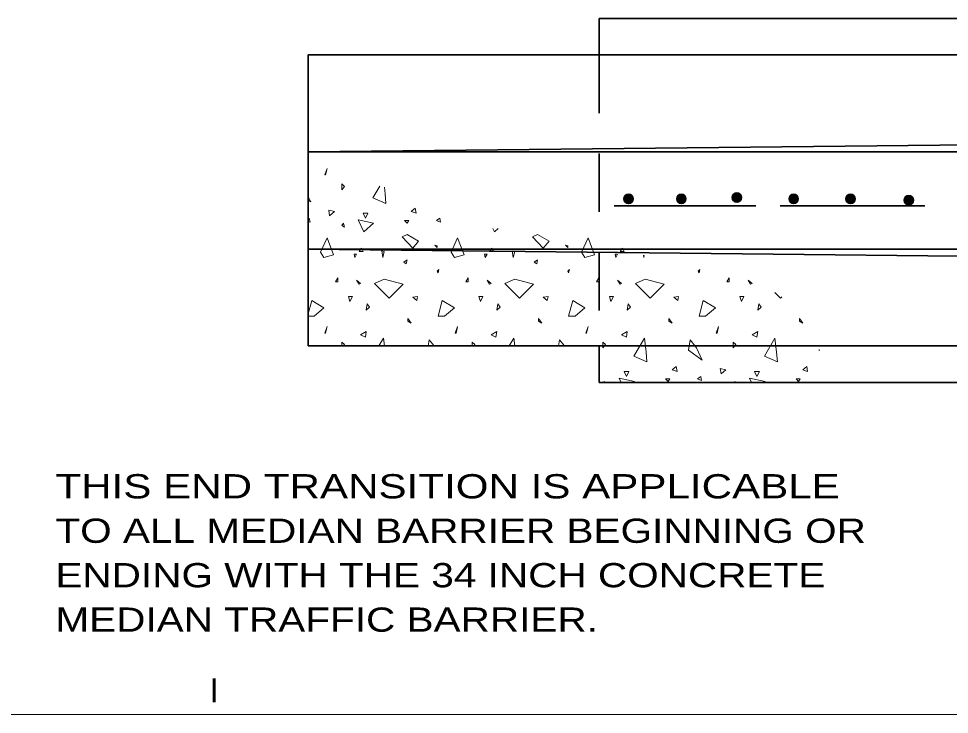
# Model space of a CAD drawing. Extents: x -11.7 to -4.5, y 8.6 to 18.8.
# Drawn here: x -9.437 to -7.133, y 16.995 to 18.716 of the extents above; entities that cross this region are included whole.
import ezdxf

# ---------------------------------------------------------------- set-up
doc = ezdxf.new("R2010")
doc.units = 0
doc.header["$LTSCALE"] = 0.024
doc.linetypes.add('LONG_DASHED', pattern=[7.5, 6, -1.5])
for name, color, linetype, lineweight in [('1', 7, 'Continuous', 35), ('10', 7, 'Continuous', 13), ('12', 7, 'Continuous', 53), ('6', 7, 'Continuous', 13)]:
    doc.layers.add(name, color=color, linetype=linetype, lineweight=lineweight)

msp = doc.modelspace()

# ---------------------------------------------------------------- linework, layer by layer
at = {"layer": '1'}
for p, q in [((-7.99983, 18.6265), (-7.99983, 18.7165)), ((-7.99983, 18.7165), (-5.59767, 18.7165)), ((-5.95783, 18.4165), (-8.71983, 18.3865)), ((-8.71983, 18.3865), (-5.95783, 18.3865)), ((-7.9625, 18.2535), (-7.61233, 18.2535)), ((-7.552, 18.2535), (-7.19333, 18.2535)), ((-8.71983, 18.14633), (-5.95783, 18.14633)), ((-8.71983, 17.90633), (-5.59933, 17.90633)), ((-7.99983, 17.81633), (-7.99983, 17.90633)), ((-7.99983, 17.81633), (-5.59767, 17.81633))]:
    msp.add_line(p, q, dxfattribs=at)
at = {"layer": '1', "linetype": 'LONG_DASHED'}
msp.add_line((-7.99983, 18.6265), (-7.99983, 17.90633), dxfattribs=at)
at = {"layer": '1'}
for points in [[(-8.71983, 17.90633), (-8.71983, 18.6265), (-5.59933, 18.6265)], [(-5.59933, 18.11633), (-5.95783, 18.11633), (-8.71983, 18.14633)]]:
    msp.add_lwpolyline(points, dxfattribs=at)
for centre, radius in [((-7.92702, 18.27033), 0.01145), ((-7.92712, 18.27042), 0.01068), ((-7.92814, 18.27042), 0.00926), ((-7.92699, 18.27015), 0.0103), ((-7.92669, 18.26967), 0.0101), ((-7.92674, 18.27003), 0.0094), ((-7.92777, 18.27087), 0.00766), ((-7.92649, 18.26997), 0.0089), ((-7.92642, 18.26972), 0.00843), ((-7.92795, 18.26997), 0.00665), ((-7.92629, 18.2696), 0.00805), ((-7.92642, 18.2694), 0.00767), ((-7.92852, 18.2696), 0.00531), ((-7.92622, 18.2694), 0.00747), ((-7.92636, 18.26952), 0.00722), ((-7.92604, 18.26934), 0.0069), ((-7.92597, 18.26947), 0.00646), ((-7.92764, 18.26985), 0.00429), ((-7.92591, 18.26954), 0.00601), ((-7.92591, 18.26967), 0.00551), ((-7.92584, 18.26952), 0.00519), ((-7.92584, 18.26947), 0.00468), ((-7.92564, 18.26907), 0.00448), ((-7.79632, 18.27033), 0.01145), ((-7.79642, 18.27042), 0.01068), ((-7.79744, 18.27042), 0.00926), ((-7.79629, 18.27015), 0.0103), ((-7.79598, 18.26967), 0.0101), ((-7.79604, 18.27003), 0.0094), ((-7.79706, 18.27087), 0.00766), ((-7.79579, 18.26997), 0.0089), ((-7.79571, 18.26972), 0.00843), ((-7.79724, 18.26997), 0.00665), ((-7.79559, 18.2696), 0.00805), ((-7.79571, 18.2694), 0.00767), ((-7.79782, 18.2696), 0.00531), ((-7.79552, 18.2694), 0.00747), ((-7.79566, 18.26952), 0.00722), ((-7.79534, 18.26934), 0.0069), ((-7.79526, 18.26947), 0.00646), ((-7.79694, 18.26985), 0.00429), ((-7.79521, 18.26954), 0.00601), ((-7.79521, 18.26967), 0.00551), ((-7.79514, 18.26952), 0.00519), ((-7.79514, 18.26947), 0.00468), ((-7.79494, 18.26907), 0.00448), ((-7.65894, 18.27369), 0.01145), ((-7.65903, 18.27378), 0.01068), ((-7.66006, 18.27378), 0.00926), ((-7.65891, 18.27351), 0.0103), ((-7.6586, 18.27303), 0.0101), ((-7.65866, 18.27339), 0.0094), ((-7.65968, 18.27423), 0.00766), ((-7.6584, 18.27333), 0.0089), ((-7.65833, 18.27308), 0.00843), ((-7.65986, 18.27333), 0.00665), ((-7.65821, 18.27296), 0.00805), ((-7.65833, 18.27276), 0.00767), ((-7.66044, 18.27296), 0.00531), ((-7.65813, 18.27276), 0.00747), ((-7.65828, 18.27288), 0.00722), ((-7.65795, 18.2727), 0.0069), ((-7.65788, 18.27283), 0.00646), ((-7.65956, 18.27321), 0.00429), ((-7.65783, 18.2729), 0.00601), ((-7.65783, 18.27303), 0.00551), ((-7.65776, 18.27288), 0.00519), ((-7.65776, 18.27283), 0.00468), ((-7.65756, 18.27243), 0.00448), ((-7.65745, 18.27238), 0.00409), ((-7.65745, 18.27249), 0.00359), ((-7.65731, 18.27258), 0.00346), ((-7.65731, 18.27225), 0.00319), ((-7.65718, 18.27251), 0.00306), ((-7.65713, 18.27243), 0.00262), ((-7.65731, 18.27263), 0.00218), ((-7.65705, 18.27236), 0.00194), ((-7.65698, 18.27238), 0.00161), ((-7.65686, 18.27231), 0.00122), ((-7.65686, 18.27243), 0.00108), ((-7.65648, 18.27238), 0.00136), ((-7.51819, 18.27037), 0.01145), ((-7.51829, 18.27046), 0.01068), ((-7.51932, 18.27046), 0.00926), ((-7.51817, 18.27019), 0.0103), ((-7.51786, 18.26971), 0.0101), ((-7.51791, 18.27007), 0.0094), ((-7.51894, 18.27091), 0.00766), ((-7.51766, 18.27001), 0.0089), ((-7.51759, 18.26976), 0.00843), ((-7.51912, 18.27001), 0.00665), ((-7.51746, 18.26964), 0.00805), ((-7.51759, 18.26944), 0.00767), ((-7.5197, 18.26964), 0.00531), ((-7.51739, 18.26944), 0.00747), ((-7.51754, 18.26956), 0.00722), ((-7.51721, 18.26938), 0.0069), ((-7.51714, 18.26951), 0.00646), ((-7.51709, 18.26958), 0.00601), ((-7.51881, 18.26989), 0.00429), ((-7.51709, 18.26971), 0.00551), ((-7.51701, 18.26956), 0.00519), ((-7.51701, 18.26951), 0.00468), ((-7.51682, 18.26911), 0.00448), ((-7.37745, 18.27037), 0.01145), ((-7.37755, 18.27046), 0.01068), ((-7.37858, 18.27046), 0.00926), ((-7.37742, 18.27019), 0.0103), ((-7.37712, 18.26971), 0.0101), ((-7.37717, 18.27007), 0.0094), ((-7.3782, 18.27091), 0.00766), ((-7.37692, 18.27001), 0.0089), ((-7.37685, 18.26976), 0.00843), ((-7.37838, 18.27001), 0.00665), ((-7.37672, 18.26964), 0.00805), ((-7.37685, 18.26944), 0.00767), ((-7.37895, 18.26964), 0.00531), ((-7.37665, 18.26944), 0.00747), ((-7.37679, 18.26956), 0.00722), ((-7.37647, 18.26938), 0.0069), ((-7.3764, 18.26951), 0.00646), ((-7.37807, 18.26989), 0.00429), ((-7.37634, 18.26958), 0.00601), ((-7.37634, 18.26971), 0.00551), ((-7.37627, 18.26956), 0.00519), ((-7.37627, 18.26951), 0.00468), ((-7.37607, 18.26911), 0.00448), ((-7.23335, 18.26701), 0.01145), ((-7.23345, 18.2671), 0.01068), ((-7.23447, 18.2671), 0.00926), ((-7.23332, 18.26683), 0.0103), ((-7.23301, 18.26635), 0.0101), ((-7.23307, 18.26671), 0.0094), ((-7.23409, 18.26755), 0.00766), ((-7.23282, 18.26665), 0.0089), ((-7.23274, 18.2664), 0.00843), ((-7.23262, 18.26628), 0.00805), ((-7.23274, 18.26608), 0.00767), ((-7.23255, 18.26608), 0.00747), ((-7.92553, 18.26902), 0.00409), ((-7.92553, 18.26913), 0.00359), ((-7.92539, 18.26922), 0.00346), ((-7.92539, 18.26889), 0.00319), ((-7.92526, 18.26915), 0.00306), ((-7.92521, 18.26907), 0.00262), ((-7.92539, 18.26927), 0.00218), ((-7.92514, 18.269), 0.00194), ((-7.92506, 18.26902), 0.00161), ((-7.92494, 18.26895), 0.00122), ((-7.92494, 18.26907), 0.00108), ((-7.92456, 18.26902), 0.00136), ((-7.92496, 18.26907), 0.000706), ((-7.92508, 18.26907), 0.000332), ((-7.92481, 18.26907), 0.000211), ((-7.79483, 18.26902), 0.00409), ((-7.79483, 18.26913), 0.00359), ((-7.79469, 18.26922), 0.00346), ((-7.79469, 18.26889), 0.00319), ((-7.79456, 18.26915), 0.00306), ((-7.79451, 18.26907), 0.00262), ((-7.79469, 18.26927), 0.00218), ((-7.79444, 18.269), 0.00194), ((-7.79436, 18.26902), 0.00161), ((-7.79424, 18.26895), 0.00122), ((-7.79424, 18.26907), 0.00108), ((-7.79386, 18.26902), 0.00136), ((-7.79426, 18.26907), 0.000706), ((-7.79438, 18.26907), 0.000332), ((-7.79411, 18.26907), 0.000211), ((-7.65687, 18.27243), 0.000706), ((-7.657, 18.27243), 0.000332), ((-7.65673, 18.27243), 0.000211), ((-7.51671, 18.26906), 0.00409), ((-7.51671, 18.26917), 0.00359), ((-7.51656, 18.26926), 0.00346), ((-7.51656, 18.26893), 0.00319), ((-7.51644, 18.26919), 0.00306), ((-7.51638, 18.26911), 0.00262), ((-7.51656, 18.26931), 0.00218), ((-7.51631, 18.26904), 0.00194), ((-7.51624, 18.26906), 0.00161), ((-7.51611, 18.26899), 0.00122), ((-7.51611, 18.26911), 0.00108), ((-7.51574, 18.26906), 0.00136), ((-7.51613, 18.26911), 0.000706), ((-7.51626, 18.26911), 0.000332), ((-7.51599, 18.26911), 0.000211), ((-7.37597, 18.26906), 0.00409), ((-7.37597, 18.26917), 0.00359), ((-7.37582, 18.26926), 0.00346), ((-7.37582, 18.26893), 0.00319), ((-7.3757, 18.26919), 0.00306), ((-7.37564, 18.26911), 0.00262), ((-7.37582, 18.26931), 0.00218), ((-7.37557, 18.26904), 0.00194), ((-7.3755, 18.26906), 0.00161), ((-7.37537, 18.26899), 0.00122), ((-7.37537, 18.26911), 0.00108), ((-7.37499, 18.26906), 0.00136), ((-7.37539, 18.26911), 0.000706), ((-7.37552, 18.26911), 0.000332), ((-7.37524, 18.26911), 0.000211), ((-7.23427, 18.26665), 0.00665), ((-7.23485, 18.26628), 0.00531), ((-7.23269, 18.2662), 0.00722), ((-7.23237, 18.26602), 0.0069), ((-7.23229, 18.26615), 0.00646), ((-7.23397, 18.26653), 0.00429), ((-7.23224, 18.26622), 0.00601), ((-7.23224, 18.26635), 0.00551), ((-7.23217, 18.2662), 0.00519), ((-7.23217, 18.26615), 0.00468), ((-7.23197, 18.26575), 0.00448), ((-7.23186, 18.2657), 0.00409), ((-7.23186, 18.26581), 0.00359), ((-7.23172, 18.2659), 0.00346), ((-7.23172, 18.26557), 0.00319), ((-7.23159, 18.26583), 0.00306), ((-7.23154, 18.26575), 0.00262), ((-7.23172, 18.26595), 0.00218), ((-7.23147, 18.26568), 0.00194), ((-7.23139, 18.2657), 0.00161), ((-7.23127, 18.26563), 0.00122), ((-7.23127, 18.26575), 0.00108), ((-7.23089, 18.2657), 0.00136), ((-7.23129, 18.26575), 0.000706), ((-7.23141, 18.26575), 0.000332), ((-7.23114, 18.26575), 0.000211)]:
    msp.add_circle(centre, radius, dxfattribs=at)
at = {"layer": '10'}
msp.add_line((-5.37917, 16.99467), (-10.32767, 16.99467), dxfattribs=at)
at = {"layer": '6'}
for points in [[(-8.6735, 18.34583), (-8.67917, 18.32967), (-8.67733, 18.32967)], [(-8.637, 18.30767), (-8.637, 18.29317), (-8.63067, 18.30133)], [(-8.66917, 18.24283), (-8.66717, 18.22883), (-8.65517, 18.239)], [(-8.58417, 18.23467), (-8.5785, 18.22267), (-8.57217, 18.23467)], [(-8.455, 18.24717), (-8.46517, 18.239), (-8.45317, 18.23467)], [(-8.637, 18.20433), (-8.63067, 18.2005), (-8.63267, 18.21067)], [(-8.59667, 18.21883), (-8.58233, 18.1885), (-8.55833, 18.21067)], [(-8.4815, 18.21683), (-8.47517, 18.21067), (-8.47133, 18.21683)], [(-8.40267, 18.21683), (-8.39267, 18.2125), (-8.3945, 18.22267)], [(-8.48767, 18.1765), (-8.46133, 18.14817), (-8.44683, 18.166), (-8.47517, 18.18233)], [(-8.16467, 18.1765), (-8.13817, 18.14817), (-8.12383, 18.166), (-8.15217, 18.18233)], [(-8.68117, 18.12567), (-8.65717, 18.13183), (-8.6735, 18.17417), (-8.68933, 18.13817)], [(-8.358, 18.12567), (-8.334, 18.13183), (-8.35033, 18.17417), (-8.36617, 18.13817)], [(-8.035, 18.12567), (-8.011, 18.13183), (-8.02733, 18.17417), (-8.04317, 18.13817)], [(-8.5885, 18.14817), (-8.58417, 18.14), (-8.59433, 18.14)], [(-8.53817, 18.142), (-8.53567, 18.12567), (-8.53183, 18.14)], [(-8.40083, 18.154), (-8.4065, 18.156), (-8.40083, 18.15017)], [(-8.26533, 18.14817), (-8.26117, 18.14), (-8.27117, 18.14)], [(-8.215, 18.142), (-8.21267, 18.12567), (-8.20883, 18.14)], [(-8.07767, 18.154), (-8.0835, 18.156), (-8.07767, 18.15017)], [(-7.94233, 18.14817), (-7.938, 18.14), (-7.948, 18.14)], [(-8.60667, 18.13383), (-8.60483, 18.12567), (-8.6005, 18.13383)], [(-8.48333, 18.11367), (-8.47767, 18.10983), (-8.47517, 18.11983)], [(-8.28367, 18.13383), (-8.28167, 18.12567), (-8.27733, 18.13383)], [(-8.16033, 18.11367), (-8.1545, 18.10983), (-8.15217, 18.11983)], [(-7.9605, 18.13383), (-7.95867, 18.12567), (-7.95433, 18.13383)], [(-8.3965, 18.0955), (-8.40083, 18.09167), (-8.39833, 18.08733)], [(-8.07333, 18.0955), (-8.07767, 18.09167), (-8.07533, 18.08733)], [(-7.75033, 18.0955), (-7.75467, 18.09167), (-7.75217, 18.08733)], [(-8.647, 18.07533), (-8.65283, 18.06517), (-8.647, 18.06517)], [(-8.59433, 18.0595), (-8.5905, 18.06133), (-8.6005, 18.0695)], [(-8.53183, 18.0715), (-8.48533, 18.0595), (-8.51983, 18.02483), (-8.55633, 18.06133)], [(-8.324, 18.07533), (-8.32967, 18.06517), (-8.324, 18.06517)], [(-8.27117, 18.0595), (-8.26733, 18.06133), (-8.27733, 18.0695)], [(-8.20883, 18.0715), (-8.16217, 18.0595), (-8.19683, 18.02483), (-8.23317, 18.06133)], [(-8.00083, 18.07533), (-8.00667, 18.06517), (-8.00083, 18.06517)], [(-7.948, 18.0595), (-7.94417, 18.06133), (-7.95433, 18.0695)], [(-7.88567, 18.0715), (-7.83917, 18.0595), (-7.87367, 18.02483), (-7.91017, 18.06133)], [(-7.67783, 18.07533), (-7.6835, 18.06517), (-7.67783, 18.06517)], [(-7.625, 18.0595), (-7.62117, 18.06133), (-7.63117, 18.0695)], [(-8.62067, 18.02867), (-8.61683, 18.01667), (-8.61067, 18.02867)], [(-8.46133, 18.02683), (-8.45117, 18.01867), (-8.44933, 18.02867)], [(-8.2975, 18.02867), (-8.29367, 18.01667), (-8.2875, 18.02867)], [(-8.13817, 18.02683), (-8.12817, 18.01867), (-8.12617, 18.02867)], [(-7.9745, 18.02867), (-7.97067, 18.01667), (-7.96433, 18.02867)], [(-7.81517, 18.02683), (-7.805, 18.01867), (-7.80317, 18.02867)], [(-7.65133, 18.02867), (-7.6475, 18.01667), (-7.64133, 18.02867)], [(-8.57417, 18.011), (-8.5765, 17.99467), (-8.56833, 18.00283)], [(-8.3825, 17.98017), (-8.358, 18.00083), (-8.38833, 18.01867), (-8.39833, 17.98017)], [(-8.251, 18.011), (-8.25333, 17.99467), (-8.24517, 18.00283)], [(-8.0595, 17.98017), (-8.035, 18.00083), (-8.06517, 18.01867), (-8.07533, 17.98017)], [(-7.92783, 18.011), (-7.93033, 17.99467), (-7.92217, 18.00283)], [(-7.73633, 17.98017), (-7.71183, 18.00083), (-7.74217, 18.01867), (-7.75217, 17.98017)], [(-7.60483, 18.011), (-7.60717, 17.99467), (-7.599, 18.00283)], [(-8.47333, 17.9745), (-8.47333, 17.96817), (-8.46517, 17.9625)], [(-8.15017, 17.9745), (-8.15017, 17.96817), (-8.142, 17.9625)], [(-7.82717, 17.9745), (-7.82717, 17.96817), (-7.819, 17.9625)], [(-7.504, 17.9745), (-7.504, 17.96817), (-7.49583, 17.9625)], [(-8.67917, 17.938), (-8.67733, 17.938), (-8.6735, 17.95433)], [(-8.35617, 17.938), (-8.35417, 17.938), (-8.35033, 17.95433)], [(-8.033, 17.938), (-8.03117, 17.938), (-8.02733, 17.95433)], [(-7.71, 17.938), (-7.708, 17.938), (-7.70417, 17.95433)], [(-8.5905, 17.93417), (-8.5785, 17.92783), (-8.5765, 17.94233)], [(-8.26733, 17.93417), (-8.25533, 17.92783), (-8.25333, 17.94233)], [(-7.94417, 17.93417), (-7.93217, 17.92783), (-7.93033, 17.94233)], [(-7.62117, 17.93417), (-7.60917, 17.92783), (-7.60717, 17.94233)], [(-7.99083, 17.91583), (-7.99083, 17.9015), (-7.9845, 17.90967)], [(-7.88367, 17.89133), (-7.88183, 17.86733), (-7.914, 17.88133), (-7.88767, 17.926)], [(-7.77483, 17.92167), (-7.77867, 17.89567), (-7.7445, 17.87117), (-7.7585, 17.9015)], [(-7.66767, 17.91583), (-7.66767, 17.9015), (-7.6615, 17.90967)], [(-7.56067, 17.89133), (-7.55867, 17.86733), (-7.59083, 17.88133), (-7.5645, 17.926)], [(-7.938, 17.84283), (-7.93217, 17.83083), (-7.926, 17.84283)], [(-7.80883, 17.85533), (-7.819, 17.84717), (-7.807, 17.84283)], [(-7.69983, 17.851), (-7.698, 17.83717), (-7.686, 17.84717)], [(-7.61483, 17.84283), (-7.60917, 17.83083), (-7.60283, 17.84283)], [(-7.48583, 17.85533), (-7.49583, 17.84717), (-7.48383, 17.84283)], [(-7.83533, 17.82517), (-7.829, 17.81883), (-7.82517, 17.82517)], [(-7.7565, 17.82517), (-7.7465, 17.82083), (-7.74833, 17.83083)], [(-7.51217, 17.82517), (-7.506, 17.81883), (-7.50217, 17.82517)]]:
    msp.add_lwpolyline(points, close=True, dxfattribs=at)
for points in [[(-8.53167, 18.299), (-8.53, 18.28317), (-8.528, 18.25917), (-8.56017, 18.273), (-8.543, 18.30217)], [(-8.71983, 18.26733), (-8.71383, 18.263), (-8.71983, 18.27617)], [(-8.71983, 18.21433), (-8.71567, 18.2125), (-8.71767, 18.22267), (-8.71983, 18.22117)], [(-8.26317, 18.19683), (-8.25917, 18.1885), (-8.25017, 18.19683)], [(-7.89033, 18.131), (-7.8895, 18.12567), (-7.88833, 18.13017)], [(-8.71983, 18.094), (-8.7195, 18.0955), (-8.71983, 18.09517)], [(-7.54733, 18.028), (-7.5505, 18.02483), (-7.56467, 18.039)], [(-8.71983, 17.98017), (-8.70567, 17.98017), (-8.68117, 18.00083), (-8.71133, 18.01867), (-8.71983, 17.98633)], [(-8.63333, 17.90633), (-8.63067, 17.90967), (-8.637, 17.91583), (-8.637, 17.90633)], [(-8.54533, 17.90633), (-8.53383, 17.926), (-8.5315, 17.90633)], [(-8.4085, 17.90633), (-8.421, 17.92167), (-8.42317, 17.90633)], [(-8.31017, 17.90633), (-8.30767, 17.90967), (-8.31383, 17.91583), (-8.31383, 17.90633)], [(-8.22233, 17.90633), (-8.21067, 17.926), (-8.2085, 17.90633)], [(-8.0855, 17.90633), (-8.09783, 17.92167), (-8.10017, 17.90633)], [(-7.45517, 17.89767), (-7.4555, 17.89567), (-7.45433, 17.89483)], [(-7.986, 17.81633), (-7.9865, 17.81883), (-7.98817, 17.81633)], [(-7.91483, 17.81633), (-7.912, 17.81883), (-7.9505, 17.827), (-7.94533, 17.81633)], [(-7.66283, 17.81633), (-7.66333, 17.81883), (-7.66517, 17.81633)], [(-7.59167, 17.81633), (-7.589, 17.81883), (-7.62733, 17.827), (-7.62233, 17.81633)]]:
    msp.add_lwpolyline(points, dxfattribs=at)

# ---------------------------------------------------------------- texts
at = {"layer": '12'}
for s, width, p in [('THIS END TRANSITION IS APPLICABLE', 1.3, (-9.346, 17.52917)), ('TO ALL MEDIAN BARRIER BEGINNING OR', 1.25, (-9.346, 17.41917)), ('ENDING WITH THE 34 INCH CONCRETE', 1.25, (-9.346, 17.30917)), ('MEDIAN TRAFFIC BARRIER.', 1.25, (-9.346, 17.19917))]:
    msp.add_text(s, height=0.06001, dxfattribs=dict(at, width=width)).set_placement(p)
msp.add_text('I', height=0.06001, dxfattribs=at).set_placement((-8.96442, 17.02417))

doc.saveas('drawing.dxf')
